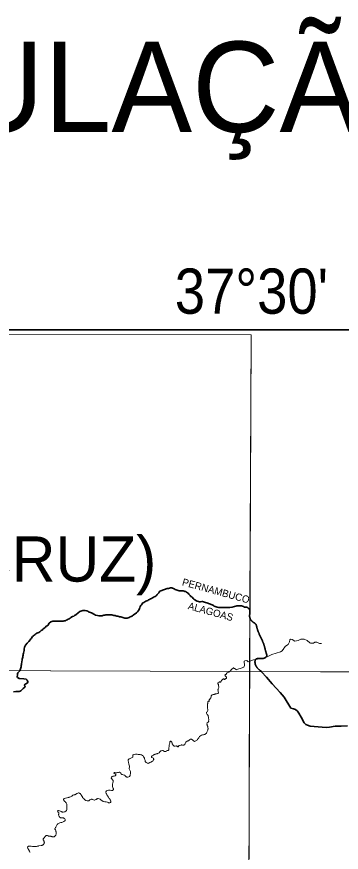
# Model space of a CAD drawing. Extents: x 553962 to 842807, y 8883888 to 9032388.
# Drawn here: x 594066 to 597653, y 8918990 to 8928234 of the extents above; entities that cross this region are included whole.
import ezdxf
from ezdxf.enums import TextEntityAlignment as Align

# ---------------------------------------------------------------- set-up
doc = ezdxf.new("R2010")
doc.units = 0
doc.header["$LTSCALE"] = 150
doc.linetypes.add('LONG_DASH_SHORT_DASH', pattern=[9.9, 6, -1.2, 1.5, -1.2])
doc.layers.add('6', color=7, linetype='Continuous', lineweight=13)

msp = doc.modelspace()

# ---------------------------------------------------------------- linework, layer by layer
at = {"layer": '6', "lineweight": 35}
msp.add_lwpolyline([(574695.3, 8924769.6), (626625.7, 8924769.6), (626625.7, 8896026.7), (574695.3, 8896026.7)], close=True, dxfattribs=at)
at = {"layer": '6'}
for points in [[(585656.3, 8924738.8), (596655.5, 8924715.8), (596639.8, 8920989.8), (585645.8, 8921027.3)], [(607600.8, 8920952.4), (596639.8, 8920989.8), (596608.8, 8909934.4), (607569.8, 8909894.9)]]:
    msp.add_lwpolyline(points, close=True, dxfattribs=at)
for points in [[(596655.5, 8924715.8), (596593.3, 8909930.3), (596531.7, 8896026.7)], [(597434.3, 8921299.7), (597411.5, 8921299.7), (597383.8, 8921313.7), (597360.5, 8921314.5), (597345.6, 8921303.6), (597314.4, 8921304.1), (597306.5, 8921308), (597277.6, 8921334.7), (597243.3, 8921349.7), (597206.9, 8921347.9), (597176.8, 8921335.1), (597140.6, 8921326.9), (597109.4, 8921345.3), (597091.8, 8921347), (597084, 8921340.9), (597080.4, 8921317.9), (597067.7, 8921289.1), (597038.2, 8921270.1), (597022.5, 8921254), (597017.6, 8921243.4), (596998.4, 8921219.3), (596982.5, 8921209.2), (596886.2, 8921177.5), (596841.4, 8921155.3), (596796, 8921139.4), (596684.4, 8921117.9), (596636.5, 8921101.1), (596623.7, 8921097.9), (596609.9, 8921111.7), (596587.7, 8921108.9), (596581.2, 8921103.5)], [(574684.9, 8921064.7), (596639.8, 8920989.8), (607636.3, 8920937.2), (626625.7, 8920820.5)], [(596581.2, 8921103.5), (596583.4, 8921058), (596577.4, 8921038.4), (596576.5, 8921036.9), (596546.9, 8921026.8), (596509.1, 8921016.7), (596491.7, 8921010.3), (596490, 8921010.8), (596472.1, 8921022.3), (596460.7, 8921029.2), (596459.6, 8921029.6), (596457.7, 8921028), (596445.2, 8921015.4), (596419.5, 8920988.9)], [(596419.5, 8920988.9), (596416.1, 8920985.5), (596411.6, 8920983.1), (596407.8, 8920981.7), (596399.5, 8920980), (596392.7, 8920976.5), (596389.8, 8920974.2), (596389.4, 8920973.2), (596388.5, 8920972.8), (596388, 8920971.8), (596387, 8920970.8), (596385.5, 8920968), (596383.2, 8920964.5), (596380.2, 8920960.7), (596376.2, 8920958.1), (596372.5, 8920956.2), (596369.6, 8920953.6), (596368.4, 8920952), (596367.4, 8920948.3), (596368.1, 8920946.1), (596368.2, 8920944.4), (596370, 8920941.5), (596371.9, 8920939.1), (596374.2, 8920937.3), (596377.3, 8920934.5), (596381, 8920931.9), (596384.8, 8920927.5), (596384.8, 8920927.5), (596385.6, 8920924.6), (596383.9, 8920916.4), (596383.6, 8920915.6), (596379.7, 8920913.5), (596373.2, 8920911.8), (596371.3, 8920906.5), (596370.2, 8920904.4), (596367.6, 8920903.1), (596364.1, 8920903.5), (596358.3, 8920907.2), (596357.3, 8920907.5), (596352.8, 8920907.7), (596347.5, 8920907.1), (596342.6, 8920904.7), (596337.1, 8920900), (596333.1, 8920895.9), (596322.9, 8920878.2)], [(596322.9, 8920878.2), (596321.8, 8920875.5), (596320.5, 8920873.2), (596315.8, 8920871.4), (596312.6, 8920871.3), (596310.4, 8920872.7), (596308.4, 8920874.5), (596303, 8920874.9), (596298.1, 8920868.6), (596293.7, 8920866.1), (596288.5, 8920862.6), (596287.3, 8920858.1), (596287.3, 8920855.8), (596289.2, 8920853.1), (596295.7, 8920846.8), (596296.2, 8920845.8), (596296.8, 8920842.9), (596295, 8920832), (596300.2, 8920819.4), (596299.3, 8920813.8), (596292.4, 8920797.3), (596290.7, 8920791.7), (596289.4, 8920786.3), (596290.7, 8920775), (596292.3, 8920769.4), (596293.4, 8920763.9), (596295.3, 8920758.3), (596294.3, 8920752.9), (596293.5, 8920751), (596289.7, 8920748.2), (596275.6, 8920744), (596269.9, 8920743.1), (596264.5, 8920741.9), (596258.8, 8920739.7), (596253.2, 8920738.4), (596247.6, 8920736.7), (596236.5, 8920735.2), (596230.9, 8920733.7), (596225.4, 8920731.3), (596218.8, 8920726.5), (596218.2, 8920725.5), (596216.7, 8920722.2), (596215.8, 8920715.7), (596215.7, 8920710.1), (596215.3, 8920707.1), (596211.6, 8920699.2), (596197.7, 8920682), (596193.8, 8920675.4), (596193.1, 8920667.7), (596194.2, 8920664.1), (596192.8, 8920660.7), (596192.2, 8920658.1), (596192, 8920658), (596185.8, 8920663.5), (596183.3, 8920663.3), (596181.1, 8920659.8), (596179.3, 8920654.3), (596178.1, 8920648.7), (596176.8, 8920637.8), (596175.7, 8920632), (596175.2, 8920626.1), (596173.4, 8920615.3), (596172.7, 8920609.8), (596172.8, 8920603.6), (596174.4, 8920586.9), (596175.3, 8920581.1), (596177.2, 8920575.1), (596177.8, 8920569.5), (596177.6, 8920563.3), (596177.3, 8920560), (596173.2, 8920551.4), (596169.7, 8920546), (596164.5, 8920539), (596163.8, 8920534.7), (596164.4, 8920529.3), (596165.8, 8920523.5), (596169.8, 8920515.6), (596179, 8920508.3), (596179.7, 8920507.3), (596181.2, 8920501.9), (596182.2, 8920495.7), (596184.6, 8920484.3), (596186.5, 8920477.5), (596189.9, 8920455.4)], [(596189.9, 8920455.4), (596189.5, 8920454.3), (596187.2, 8920440.2), (596187.2, 8920439.4), (596188.3, 8920437.7), (596188.3, 8920437.1), (596185.5, 8920433.8), (596181.5, 8920430.2), (596172.4, 8920423), (596169.5, 8920418.8), (596168.2, 8920412.8), (596168.7, 8920407.7), (596169.5, 8920402.7), (596172, 8920392.7), (596176.5, 8920381.4), (596178, 8920376.9), (596179.2, 8920371.6), (596180.6, 8920361.1), (596180.6, 8920356.3), (596179.6, 8920351.4), (596176.7, 8920340.8), (596168, 8920320.1), (596162.5, 8920310), (596158.8, 8920305.4), (596153.7, 8920300.7), (596148.8, 8920297.3), (596144, 8920294.9), (596139.2, 8920293.3), (596128.6, 8920290.9), (596118.2, 8920289.7), (596108.2, 8920286.6), (596097.6, 8920278.6)], [(595936.7, 8920206.9), (595936.6, 8920206.9), (595929.1, 8920195.6), (595929.2, 8920192.4), (595927.8, 8920190.1), (595924, 8920185.5), (595919.5, 8920180.9), (595916.5, 8920178.5), (595912.4, 8920177.2), (595907.3, 8920176.2), (595897.2, 8920177), (595891.9, 8920177.8), (595886.4, 8920177.8), (595881.6, 8920177.2), (595866.2, 8920173.5), (595861.1, 8920171.8), (595856.2, 8920168.8), (595848.9, 8920158.8), (595845, 8920158), (595843.1, 8920159.2), (595839.4, 8920163), (595833.5, 8920165.6), (595828.2, 8920166.5), (595818.6, 8920165.9), (595813.1, 8920165), (595806.4, 8920165.6), (595802.8, 8920167.3), (595797.3, 8920170.8), (595790.6, 8920180), (595786.8, 8920186.4), (595784.7, 8920191.3), (595784, 8920196.7), (595782.1, 8920201.6), (595779.5, 8920206.9), (595776.4, 8920211.9), (595772.8, 8920216), (595770, 8920218), (595764.9, 8920219.3), (595762.9, 8920219.2), (595760.1, 8920216.5), (595757.9, 8920212.1), (595756.5, 8920201.4), (595753, 8920186.6), (595752.3, 8920180.9), (595752.1, 8920171), (595750.8, 8920165.7), (595749.5, 8920155.6), (595748.2, 8920150.3), (595746.6, 8920135.4), (595747, 8920125.1), (595746.8, 8920123), (595744.1, 8920119), (595741.7, 8920117.9), (595733.7, 8920117.9), (595729, 8920117.3), (595726.8, 8920116.5), (595726.1, 8920116), (595719.5, 8920108.7), (595714.6, 8920105.7), (595709.3, 8920104.6), (595704.2, 8920104.7), (595697.4, 8920106.1), (595682.2, 8920114.9), (595680.4, 8920115.5), (595675.5, 8920115.9), (595665.3, 8920114.4), (595660.3, 8920112.3), (595658.1, 8920111)], [(596097.6, 8920278.6), (596087, 8920270.7), (596086.2, 8920270.4), (596080.9, 8920262.8), (596078.5, 8920257.9), (596076, 8920254.4), (596072.4, 8920250.1), (596065.8, 8920243.2), (596064.1, 8920240.6), (596063, 8920236.2), (596030, 8920216.7), (596014.6, 8920225.9), (596013.7, 8920226.2), (596013.1, 8920226.8), (596012.8, 8920227.7), (596010.9, 8920229.4), (596007.9, 8920232.8), (596000.2, 8920239.7), (595996.7, 8920242.2), (595992.4, 8920243.5), (595988.7, 8920243.2), (595985.4, 8920242.5), (595983.7, 8920241.8), (595981.6, 8920239.6), (595976.4, 8920232.6), (595973.2, 8920229.4), (595969.3, 8920226.3), (595963.4, 8920223.6), (595959.7, 8920222.4), (595955.7, 8920221.9), (595952, 8920221.1), (595948.5, 8920221.1), (595947.7, 8920220.8), (595944.7, 8920218.6), (595940.5, 8920213.8), (595940.1, 8920212.7), (595939.1, 8920212), (595936.7, 8920206.9)], [(595556.2, 8920051.1), (595556.8, 8920041.8), (595557.1, 8920040.8), (595558.3, 8920039.9), (595568.7, 8920036.2), (595571.6, 8920035), (595576.8, 8920030.7), (595578.9, 8920025.4), (595579.7, 8920020.2), (595579.8, 8920016.6), (595579.2, 8920014.4), (595568.5, 8919999.7), (595567.3, 8919998.5), (595548.1, 8919986.8), (595541.1, 8919985.3), (595535.4, 8919982.4), (595524.6, 8919976), (595518.6, 8919974.3), (595513.3, 8919975), (595502.3, 8919979.2), (595495.2, 8919983.1), (595491.5, 8919987.2), (595486.8, 8919994.6), (595485.2, 8920000.2), (595484.5, 8920006.3), (595481.8, 8920018), (595479.4, 8920024.2), (595478.1, 8920030.1), (595476.1, 8920035.8), (595474.8, 8920037.4), (595472.3, 8920042.5), (595468.9, 8920048.1), (595462.9, 8920056.2), (595457.2, 8920059.5), (595444.2, 8920067.7), (595436.6, 8920069.9), (595431.2, 8920071), (595425.4, 8920071.8), (595413.3, 8920072.9), (595407.1, 8920073.8), (595395.5, 8920074.6), (595383.1, 8920075.9), (595377.1, 8920075.5), (595365.3, 8920073.2), (595359.7, 8920071.7), (595353.5, 8920068.5), (595349.8, 8920066.3), (595348.4, 8920064.4), (595347.6, 8920062.5), (595348.1, 8920060.6), (595350.5, 8920055.3), (595350.7, 8920050.2), (595349.1, 8920044.4), (595347.4, 8920041.8), (595332.8, 8920034.6), (595319.8, 8920029.3), (595308.8, 8920025.2), (595303.6, 8920020.4), (595296.8, 8920012.5), (595296.3, 8920010.1), (595296.8, 8920002), (595298.6, 8919998.5), (595301.1, 8919990.6), (595302.4, 8919978.8), (595303.5, 8919972.9), (595306.1, 8919966.4), (595309.8, 8919954.2), (595311.2, 8919942.8), (595312.2, 8919936.4), (595312.2, 8919930.6), (595310.5, 8919919.3), (595310.5, 8919914.1), (595312, 8919907.4), (595321.5, 8919891.2), (595322.7, 8919885.4), (595322.1, 8919874.5), (595322.3, 8919868.3), (595321.6, 8919856.8), (595320.8, 8919850.8), (595321, 8919844.9), (595319.8, 8919839.6), (595317.8, 8919835.8), (595315.7, 8919833.1), (595311, 8919828.8), (595304.7, 8919824.7), (595293.7, 8919822.5), (595287.7, 8919822.5), (595281.7, 8919822.9), (595279.6, 8919823.3), (595276.1, 8919825.3), (595270.4, 8919830.6), (595265.5, 8919837.5), (595259.1, 8919843.4), (595253.4, 8919845.2), (595241.8, 8919847.7), (595235.8, 8919849.4), (595229.3, 8919851.8), (595224.2, 8919853.9), (595221.7, 8919855.6), (595215.5, 8919865.8), (595211.5, 8919869.9)], [(595658.1, 8920111), (595655.6, 8920108.5), (595651.9, 8920104.2), (595647.8, 8920100.6), (595639.3, 8920091), (595632.7, 8920087), (595623.2, 8920082.6), (595617.5, 8920080.8), (595612.7, 8920078.9), (595606.8, 8920078.2), (595597.1, 8920075.8), (595591.6, 8920073.9), (595586.7, 8920071), (595581.7, 8920067.6), (595577.1, 8920064.8), (595571.5, 8920062.6), (595561.7, 8920056.4), (595561.7, 8920056.4), (595556.2, 8920051.1)], [(595211.5, 8919869.9), (595211.5, 8919869.9), (595203.4, 8919875.3), (595196.7, 8919875.5), (595191.1, 8919874.5), (595185.1, 8919873.9), (595179.1, 8919872.2), (595173.5, 8919871.2), (595167, 8919870.5), (595163.5, 8919870.5), (595160.9, 8919871.1), (595149.3, 8919873), (595145.9, 8919872.6), (595141.2, 8919869.2), (595140.4, 8919866.2), (595140.9, 8919864.8), (595142, 8919862.9), (595154.1, 8919858.3), (595158.4, 8919853), (595159.9, 8919850), (595160.5, 8919846.3), (595160.3, 8919843.4), (595158.2, 8919840.8), (595152.4, 8919836.5), (595141.6, 8919833.3), (595135.4, 8919832.3), (595129.5, 8919831.1), (595122.5, 8919828.4), (595116, 8919824.6), (595113.1, 8919821.6), (595112.2, 8919820.4), (595109.5, 8919814.4), (595109.6, 8919812.9), (595111.6, 8919808.8), (595130.3, 8919784.6), (595131.4, 8919769.3), (595127.8, 8919758.5), (595126.5, 8919753.3), (595126, 8919748), (595123.7, 8919733.2), (595123.5, 8919727.1), (595123.7, 8919722.3), (595124.3, 8919717.4), (595126.6, 8919707.1), (595129.1, 8919701.7), (595132.3, 8919696.5), (595134.2, 8919691.2), (595134.9, 8919686.4), (595133.1, 8919680.8), (595132.3, 8919679.5), (595128.7, 8919677), (595125.3, 8919675.6), (595120.4, 8919674.8), (595115, 8919674.6), (595100.3, 8919676.1), (595094.8, 8919676.1), (595089.5, 8919676.5), (595084.5, 8919676.3), (595079.2, 8919676.5), (595069.2, 8919674.8), (595059.4, 8919670.2), (595055.8, 8919667.6), (595053.5, 8919663.7), (595052, 8919657.7), (595052.1, 8919654.1), (595055.6, 8919642.4), (595057.9, 8919637.1), (595059.3, 8919631.8), (595061.3, 8919625.8), (595063.1, 8919624.4), (595064.1, 8919622.7), (595069.5, 8919614.9), (595072.4, 8919609.9), (595076.3, 8919605.2), (595080.2, 8919598.6), (595084.2, 8919593.5), (595088.7, 8919586.8), (595092.6, 8919582.8), (595096.9, 8919576.3), (595099.5, 8919571.6), (595104.2, 8919560.8), (595105.8, 8919556), (595106, 8919550.3), (595104.9, 8919544.2), (595104.4, 8919543.4), (595101.4, 8919540.4), (595096.4, 8919537.1), (595091.3, 8919536.3), (595085.6, 8919536.5), (595079.3, 8919538.1), (595076.2, 8919540.5), (595069.8, 8919543.9), (595053.4, 8919547.8), (595038.5, 8919547.9)], [(594635, 8919595.8), (594624.9, 8919592.5), (594619.4, 8919591.1), (594604.2, 8919588.8), (594593.8, 8919586.4), (594587.8, 8919584), (594585.7, 8919579.6), (594584.3, 8919574.8), (594584.1, 8919571.4), (594587.7, 8919564.4), (594590.8, 8919560), (594596.2, 8919553.6), (594605.1, 8919547.1), (594605.3, 8919546), (594606.5, 8919545.2), (594610.9, 8919538.4), (594616.3, 8919531.4), (594619.9, 8919521.3), (594620.2, 8919515.6), (594618.5, 8919500.2), (594620, 8919480), (594620.2, 8919469.6), (594619.8, 8919464.6), (594619, 8919459.8), (594616.9, 8919454.2), (594615.9, 8919452.5), (594614.8, 8919452.1), (594612.8, 8919449.7), (594607.4, 8919445.2), (594602.9, 8919441.7), (594598.5, 8919439.5), (594592.9, 8919437.8), (594578.2, 8919435.6), (594572.5, 8919436), (594567.4, 8919437), (594562.2, 8919439.2), (594557.3, 8919442)], [(595038.5, 8919547.9), (595038.5, 8919547.9), (595023.6, 8919553.8), (595021, 8919554), (594997.1, 8919569.7), (594992.7, 8919574.4), (594988.3, 8919577.5), (594983.2, 8919579.3), (594977.9, 8919580.7), (594967.4, 8919584.3), (594967.4, 8919584.3), (594962.5, 8919584), (594957.2, 8919582.7), (594952.2, 8919580.4), (594942.3, 8919574.2), (594931.7, 8919569.5), (594926.3, 8919568.6), (594921, 8919568.3), (594916.2, 8919569.5), (594900.8, 8919574.8), (594896.1, 8919576.2), (594890.9, 8919576.6), (594889, 8919576.3), (594880.2, 8919572.8), (594875.3, 8919569.6), (594870.1, 8919565.6), (594866.2, 8919563.1), (594861.2, 8919560.8), (594855.5, 8919559.2), (594850.6, 8919559), (594845, 8919559.4), (594835.2, 8919562.7), (594830.2, 8919564.8), (594824.9, 8919567.4), (594820.3, 8919570.2), (594811.4, 8919577.8), (594807, 8919583.8), (594798.1, 8919593.9), (594794.3, 8919597.8), (594791.6, 8919603.4), (594788, 8919608), (594780.1, 8919619.3), (594777, 8919624.9), (594773.5, 8919629.2), (594769.1, 8919635.6), (594765.6, 8919640.1), (594763.3, 8919642.3), (594758.6, 8919644.9), (594751.6, 8919646.6), (594748.7, 8919646.7), (594741, 8919644.8), (594731.3, 8919640.1), (594716.2, 8919630.9), (594710.7, 8919628.3), (594708.7, 8919627.7), (594700.3, 8919627), (594695.4, 8919625.8), (594690.4, 8919623.9), (594685.2, 8919620.5), (594675.3, 8919612.9), (594666.2, 8919607.6), (594660.5, 8919605.2), (594645.4, 8919599.5), (594640.1, 8919598), (594635, 8919595.8)], [(594557.3, 8919442), (594551.1, 8919444.5), (594539.1, 8919448.8), (594529, 8919450.9), (594523.7, 8919450.9), (594521.8, 8919450.5), (594518.6, 8919448.1), (594517, 8919443.7), (594519, 8919439.4), (594520.5, 8919437), (594525.3, 8919433.8), (594525.3, 8919433.8), (594529.7, 8919430.2), (594531.2, 8919428.5), (594532.1, 8919425.1), (594532.7, 8919419.8), (594532.4, 8919417.8), (594530.1, 8919413.8), (594529.5, 8919408.7), (594529.5, 8919403), (594530.3, 8919397.9), (594531, 8919395.7), (594533, 8919392.5), (594535.7, 8919387.3), (594538.8, 8919382.7), (594543.6, 8919377), (594545.6, 8919375.7), (594551.1, 8919373.3), (594576.7, 8919371.7), (594582.3, 8919370.2), (594586.9, 8919367.9), (594591.9, 8919363.6), (594597, 8919358.8), (594601.1, 8919353.4), (594602, 8919350), (594601.8, 8919346.9), (594599.9, 8919341.8), (594598.6, 8919339), (594588.3, 8919331.5), (594580.2, 8919327.7), (594573.2, 8919325.4), (594563.1, 8919321), (594552.8, 8919318.4), (594542.7, 8919314.8), (594527.7, 8919307.4), (594522.1, 8919303.5), (594514.1, 8919296.6), (594510.3, 8919291.4), (594502.3, 8919274.3), (594499.6, 8919269.1), (594496.3, 8919263.8), (594489.6, 8919254.4), (594489, 8919253.2), (594488.6, 8919248.2), (594488.8, 8919245.4), (594490.3, 8919242.4), (594494, 8919237.2), (594496.5, 8919232.2), (594499.4, 8919222.1), (594500.3, 8919216.8), (594500.8, 8919206.3), (594500.1, 8919191.2), (594498.4, 8919183.1), (594497, 8919178.8), (594490.3, 8919171)], [(594490.3, 8919171), (594484.4, 8919165.8), (594480.2, 8919163.1), (594477.6, 8919161.8), (594469.8, 8919160.7), (594464.5, 8919161.2), (594459.5, 8919162.6), (594454.8, 8919164.9), (594447.9, 8919165.8), (594442.9, 8919167), (594432.3, 8919167.1), (594422.2, 8919168.6), (594417, 8919170.4), (594415.2, 8919171.5), (594414.2, 8919172.6), (594407, 8919176), (594402, 8919176.9), (594396.7, 8919176.5), (594395.1, 8919175.8), (594391.6, 8919175), (594386.4, 8919172.1), (594382.7, 8919167.2), (594378.2, 8919161.7), (594374, 8919155.7), (594365.4, 8919145.8), (594359, 8919139.7), (594358.8, 8919137.6), (594358.1, 8919135.4), (594358.9, 8919129.4), (594361.1, 8919124.1), (594364, 8919119.2), (594367.4, 8919114), (594369.6, 8919108.9), (594370.9, 8919103.1), (594371.3, 8919098.6), (594370.9, 8919093.8), (594370, 8919092.2)], [(594370, 8919092.2), (594368.7, 8919088), (594365.9, 8919083.2), (594362.2, 8919077.9), (594358.5, 8919074.3), (594356.6, 8919073), (594355.7, 8919072.7), (594354.9, 8919071.8), (594351.9, 8919070.4), (594346.7, 8919067.3), (594341.7, 8919065.7), (594336.4, 8919065.2), (594336.4, 8919065.2), (594306.8, 8919060.6), (594305.6, 8919059.7), (594301.6, 8919059.8), (594291, 8919058.2), (594282.8, 8919054.8), (594279.1, 8919053.6), (594275.2, 8919052.8), (594264, 8919052.8), (594259.8, 8919053.2), (594241.1, 8919053.8), (594225.3, 8919057.9), (594218.1, 8919058.5), (594210.2, 8919059.6), (594206.2, 8919059.4), (594202, 8919058.4), (594197, 8919057.8), (594190.4, 8919051.7), (594187.7, 8919049.6), (594185.5, 8919047.1), (594184.7, 8919043.1), (594185, 8919041.9), (594187.9, 8919036.1), (594190, 8919032.9), (594198.1, 8919016.4), (594199.7, 8919012.4), (594205.6, 8919001), (594211, 8918993.2), (594213.8, 8918990.1)]]:
    msp.add_lwpolyline(points, dxfattribs=at)
at = {"layer": '6', "linetype": 'LONG_DASH_SHORT_DASH', "lineweight": 35}
for points in [[(595503.7, 8921771.9), (595513.3, 8921776.4), (595523.8, 8921783.5), (595533.3, 8921787.6), (595542.8, 8921794.6), (595554.8, 8921799.7), (595565.9, 8921806.8), (595575.4, 8921810.3), (595584.9, 8921816.9), (595595.4, 8921821), (595607, 8921827), (595613.5, 8921834.6), (595619.5, 8921842.7), (595626.5, 8921849.7), (595635, 8921860.3), (595640.5, 8921868.3), (595647.9, 8921877.9), (595660, 8921882.5), (595669.5, 8921886.5), (595678, 8921891.1), (595709.1, 8921900.8), (595718.1, 8921904.3), (595730.2, 8921907.9), (595742.2, 8921908.9), (595753.8, 8921913), (595767.3, 8921916.1), (595779.9, 8921915.6), (595789.4, 8921912.7), (595799, 8921909.2), (595806.5, 8921903.2), (595816.6, 8921897.7), (595827.1, 8921893.8), (595861.3, 8921882.9), (595871.9, 8921882.9), (595892.5, 8921882), (595904, 8921881.1), (595916.1, 8921878.1), (595925.6, 8921877.1), (595934.7, 8921873.7), (595943.7, 8921867.2), (595952.3, 8921861.7), (595960.3, 8921855.2), (595968.4, 8921847.7), (595974, 8921838.7), (595983.5, 8921831.2), (595990.1, 8921821.7), (596000.2, 8921815.7), (596007.7, 8921809.2), (596016.8, 8921798.7), (596024.9, 8921790.7), (596035.4, 8921784.8), (596052.1, 8921771.8), (596061.6, 8921768.8), (596073.7, 8921763.3), (596085.2, 8921760.4), (596097.3, 8921760.4), (596110.3, 8921764.5), (596119.9, 8921763.6), (596131.4, 8921760.1), (596142.5, 8921759.1), (596153.6, 8921753.2), (596165.6, 8921749.7), (596176.7, 8921745.2), (596186.7, 8921741.8), (596208.8, 8921735.8), (596232, 8921724.4), (596241.6, 8921720.9), (596249.1, 8921714.9), (596268.7, 8921704.5), (596279.8, 8921701), (596294.3, 8921698.1), (596306.9, 8921697.1), (596320, 8921696.7), (596353.6, 8921696.8), (596389.2, 8921699), (596420.4, 8921700.1), (596448.5, 8921702.3), (596474.6, 8921709.4), (596486.1, 8921713.5), (596497.6, 8921717), (596508.2, 8921718.1), (596528.7, 8921718.2), (596538.8, 8921717.7), (596549.8, 8921716.3), (596560.4, 8921712.3), (596572.5, 8921708.8), (596585, 8921703.4), (596598.6, 8921701.4), (596611.6, 8921701.5)], [(594412.5, 8921504.4), (594417, 8921514), (594424.5, 8921525.1), (594441.5, 8921540.7), (594453.5, 8921543.8), (594464, 8921547.8), (594495.2, 8921548), (594509.2, 8921547.5), (594523.3, 8921547.6), (594543.9, 8921545.7), (594569, 8921545.8), (594580.6, 8921546.3), (594590.1, 8921549.9), (594603.7, 8921551.5), (594614.2, 8921558.1), (594625.2, 8921562.1), (594636.2, 8921569.7), (594646.8, 8921574.3), (594657.3, 8921581.8), (594664.3, 8921588.9), (594683.8, 8921599), (594696.4, 8921604.1), (594705.9, 8921609.2), (594718.4, 8921616.8), (594744.4, 8921639), (594765, 8921654.6), (594774, 8921659.2), (594786.5, 8921662.7), (594796.6, 8921666.8), (594808.1, 8921666.8), (594820.7, 8921664.4), (594841.3, 8921661.5), (594851.3, 8921657), (594860.9, 8921651), (594870.5, 8921647.1), (594883, 8921642.6), (594893.1, 8921638.6), (594925.8, 8921621.2), (594936.4, 8921614.7), (594958, 8921608.3), (594972.1, 8921605.8), (594986.1, 8921605.9), (594998.2, 8921606.4), (595010.2, 8921606.5), (595019.3, 8921610.1), (595029.8, 8921613.6), (595040.8, 8921614.7), (595049.9, 8921618.2), (595059.9, 8921618.8), (595070, 8921618.8), (595081.5, 8921618.4), (595106.1, 8921616.5), (595118.7, 8921616), (595128.2, 8921612.6), (595140.3, 8921610.1), (595153.9, 8921608.2), (595162.9, 8921604.7), (595173.5, 8921601.7), (595183, 8921600.8), (595193.1, 8921600.3), (595203.6, 8921596.8), (595217.2, 8921593.9), (595226.7, 8921592.9), (595259.9, 8921582), (595287, 8921582.1), (595309.1, 8921588.3), (595319.1, 8921594.3), (595331.2, 8921597.9), (595343.7, 8921605.5), (595354.2, 8921612.6), (595388.8, 8921638.3), (595402.3, 8921649.4), (595410.8, 8921664.5), (595419.2, 8921676.6), (595423.7, 8921686.2), (595427.2, 8921695.2), (595430.2, 8921707.8), (595437.2, 8921719.8), (595444.2, 8921729.4), (595460.7, 8921748.6), (595469.7, 8921754.1), (595481.2, 8921762.2), (595491.7, 8921767.8), (595503.7, 8921771.9)], [(594099.8, 8920996.9), (594100.5, 8921000.4), (594104, 8921009.5), (594109.4, 8921021.6), (594109.9, 8921032.1), (594113.9, 8921042.7), (594114.8, 8921055.2), (594118.3, 8921067.8), (594119.8, 8921079.9), (594121.7, 8921092.4), (594121.7, 8921102.5), (594125.7, 8921114.5), (594126.1, 8921125.6), (594130.1, 8921136.6), (594133.6, 8921148.2), (594134.5, 8921159.3), (594138, 8921170.8), (594138.5, 8921180.4), (594142.4, 8921191.4), (594146.8, 8921222.6), (594147.8, 8921236.1), (594153.7, 8921261.3), (594160.2, 8921273.3), (594164.2, 8921283.4), (594181.7, 8921304.6), (594199.2, 8921321.7), (594213.7, 8921339.4), (594222.2, 8921350.9), (594228.2, 8921360.5), (594241.7, 8921377.7), (594249.7, 8921386.2), (594257.7, 8921393.3), (594269.2, 8921400.9), (594278.7, 8921405.9), (594289.8, 8921413), (594300.8, 8921417.1), (594311.8, 8921422.1), (594322.3, 8921429.7), (594337.9, 8921443.3), (594348.4, 8921448.4), (594354.9, 8921457.5), (594365.9, 8921466.1), (594384.9, 8921482.7), (594392.4, 8921491.3), (594401.5, 8921496.3), (594412.5, 8921504.4)], [(594176.2, 8920899.4), (594168.7, 8920905.5), (594145.6, 8920910), (594098.9, 8920911.9), (594091.7, 8920913.9), (594073.9, 8920925.8), (594070.1, 8920934.3), (594074.3, 8920949.1), (594073.3, 8920964.4), (594077, 8920974.4), (594099.8, 8920996.9)], [(596772.7, 8920987.6), (596827.2, 8920927.7), (596887.6, 8920854.4), (596978.3, 8920759.7), (597020.1, 8920705.3), (597096.6, 8920585), (597125.2, 8920577.1), (597146.5, 8920568.5), (597170.2, 8920550.2), (597184.9, 8920530.7), (597208.4, 8920486.7), (597244.6, 8920421.2), (597260.6, 8920405.6), (597280.5, 8920395.7), (597310.8, 8920386.4), (597353.9, 8920380.3), (597487.5, 8920372), (597521, 8920374.3), (597585, 8920384.1), (597610.2, 8920386.4), (597650.2, 8920385.4), (597721.8, 8920389.3)], [(594030.9, 8920764), (594054.9, 8920770.3), (594073.9, 8920770.6), (594092, 8920768.1), (594103, 8920771.6), (594111.8, 8920776.3), (594138.2, 8920802.2), (594156.9, 8920817.3), (594159.3, 8920821.2), (594159, 8920825), (594150, 8920833.8), (594150.8, 8920840.9), (594161, 8920850.4), (594174.3, 8920856.6), (594180.7, 8920861.6), (594187.3, 8920871.1), (594189.3, 8920877.9), (594182.3, 8920894.6), (594176.2, 8920899.4)]]:
    msp.add_lwpolyline(points, dxfattribs=at)
msp.add_spline([(596611.2, 8921701.9), (596639.9, 8921673.2), (596639.9, 8921601.6), (596665.6, 8921547.2), (596711.4, 8921507.1), (596720, 8921478.5), (596734.3, 8921432.6), (596788.7, 8921312.3), (596811.6, 8921237.9), (596823.1, 8921194.9), (596828.8, 8921163.4), (596788.7, 8921134.8), (596705.7, 8921123.3), (596700, 8921083.2), (596772.7, 8920987.6)], degree=3, dxfattribs=at)

# ---------------------------------------------------------------- texts
at = {"layer": '6'}
msp.add_text('ARTICULAÇÃO DAS CARTAS 1:100.000', height=1000, dxfattribs=at).set_placement((601765.5, 8926958.2), align=Align.CENTER)
at = {"layer": '6', "width": 0.9}
msp.add_text("37°30'", height=500, dxfattribs=at).set_placement((596659.7, 8924948.5), align=Align.CENTER)
at = {"layer": '6'}
msp.add_text('(POÇO DA CRUZ)', height=500, dxfattribs=at).set_placement((590036.9, 8921984.9))
for s, p in [('PERNAMBUCO', (596257.1, 8921844)), ('ALAGOAS', (596198.5, 8921614.1))]:
    msp.add_text(s, height=80, rotation=344.671, dxfattribs=at).set_placement(p, align=Align.CENTER)

doc.saveas('drawing.dxf')
